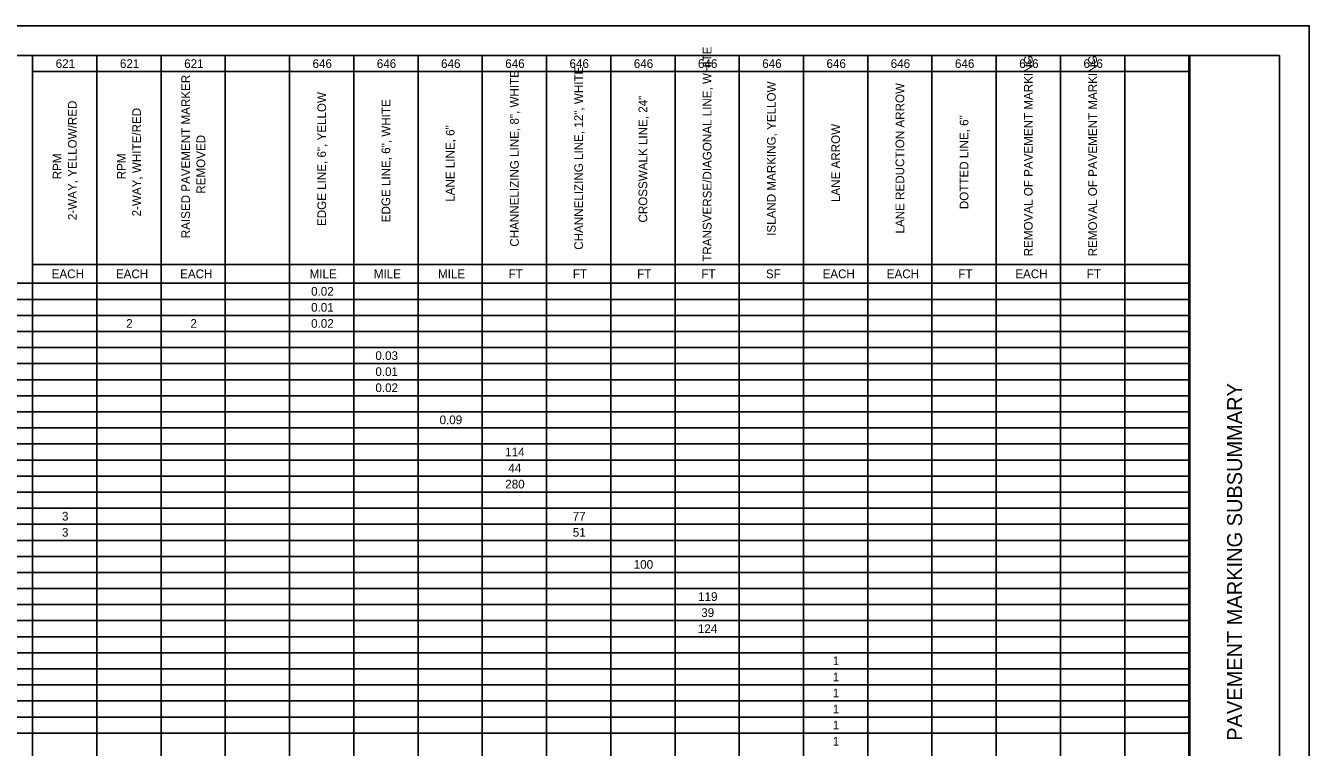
# Model space of a CAD drawing. Extents: x 0 to 34, y 0 to 22.
# Drawn here: x 12.53 to 34, y 9.93 to 22 of the extents above; entities that cross this region are included whole.
import ezdxf

# ---------------------------------------------------------------- set-up
doc = ezdxf.new("R2010")
doc.units = 0
for name, color, linetype in [('SH_Border', 7, 'Continuous'), ('SH_Cut_Line', 7, 'Continuous'), ('SH_Data', 7, 'Continuous'), ('SH_Text', 7, 'Continuous')]:
    doc.layers.add(name, color=color, linetype=linetype)

msp = doc.modelspace()

# ---------------------------------------------------------------- linework, layer by layer
at = {"layer": 'SH_Border'}
msp.add_line((32, 0.5), (32, 21.5), dxfattribs=at)
msp.add_lwpolyline([(1.5, 21.5), (33.5, 21.5), (33.5, 0.5), (1.5, 0.5)], close=True, dxfattribs=at)
at = {"layer": 'SH_Cut_Line'}
msp.add_lwpolyline([(0, 0), (34, 0), (34, 22), (0, 22)], close=True, dxfattribs=at)
at = {"layer": 'SH_Text'}
for p, q in [((1.5, 21.5), (31.986, 21.5)), ((12.642, 21.5), (12.642, 0.496)), ((13.717, 21.5), (13.717, 0.765)), ((14.791, 21.5), (14.791, 0.496)), ((15.866, 21.5), (15.866, 0.496)), ((16.941, 21.5), (16.941, 0.496)), ((18.015, 21.5), (18.015, 0.765)), ((19.09, 21.5), (19.09, 0.496)), ((20.165, 21.5), (20.165, 0.496)), ((21.239, 21.5), (21.239, 0.496)), ((22.314, 21.5), (22.314, 0.496)), ((23.389, 21.5), (23.389, 0.496)), ((24.463, 21.5), (24.463, 0.496)), ((25.538, 21.5), (25.538, 0.496)), ((26.613, 21.5), (26.613, 0.496)), ((27.687, 21.5), (27.687, 0.496)), ((28.762, 21.5), (28.762, 0.496)), ((29.837, 21.5), (29.837, 0.496)), ((30.911, 21.5), (30.911, 0.496)), ((31.986, 21.5), (31.986, 0.496)), ((12.642, 21.231), (31.986, 21.231)), ((12.642, 18.007), (31.986, 18.007)), ((1.5, 17.691), (31.986, 17.691)), ((1.5, 17.423), (31.986, 17.423)), ((1.5, 17.154), (31.986, 17.154)), ((1.5, 16.885), (31.986, 16.885)), ((1.5, 16.617), (31.986, 16.617)), ((1.5, 16.348), (31.986, 16.348)), ((1.5, 16.079), (31.986, 16.079)), ((1.5, 15.811), (31.986, 15.811)), ((1.5, 15.542), (31.986, 15.542)), ((1.5, 15.273), (31.986, 15.273)), ((1.5, 15.005), (31.986, 15.005)), ((1.5, 14.736), (31.986, 14.736)), ((1.5, 14.467), (31.986, 14.467)), ((1.5, 14.198), (31.986, 14.198)), ((1.5, 13.93), (31.986, 13.93)), ((1.5, 13.661), (31.986, 13.661)), ((1.5, 13.392), (31.986, 13.392)), ((1.5, 13.124), (31.986, 13.124)), ((1.5, 12.855), (31.986, 12.855)), ((1.5, 12.586), (31.986, 12.586)), ((1.5, 12.318), (31.986, 12.318)), ((1.5, 12.049), (31.986, 12.049)), ((1.5, 11.78), (31.986, 11.78)), ((1.5, 11.512), (31.986, 11.512)), ((1.5, 11.243), (31.986, 11.243)), ((1.5, 10.974), (31.986, 10.974)), ((1.5, 10.706), (31.986, 10.706)), ((1.5, 10.437), (31.986, 10.437)), ((1.5, 10.168), (31.986, 10.168))]:
    msp.add_line(p, q, dxfattribs=at)

# ---------------------------------------------------------------- texts
at = {"layer": 'SH_Data'}
msp.add_text('PAVEMENT MARKING SUBSUMMARY', height=0.25, rotation=90, dxfattribs=at).set_placement((32.875, 10.041))
at = {"layer": 'SH_Text'}
for s, p in [('TRANSVERSE/DIAGONAL LINE, WHITE', (23.999, 18.053)), ('REMOVAL OF PAVEMENT MARKING', (29.372, 18.143)), ('REMOVAL OF PAVEMENT MARKING', (30.447, 18.143)), ('CHANNELIZING LINE, 12", WHITE', (21.849, 18.252)), ('RAISED PAVEMENT MARKER ', (15.274, 18.445)), ('CHANNELIZING LINE, 8", WHITE', (20.775, 18.304)), ('ISLAND MARKING, YELLOW', (25.073, 18.485)), ('EDGE LINE, 6", YELLOW', (17.551, 18.649)), ('LANE REDUCTION ARROW', (27.223, 18.524)), ('2-WAY, YELLOW/RED', (13.379, 18.748)), ('2-WAY, WHITE/RED', (14.454, 18.81)), ('EDGE LINE, 6", WHITE', (18.625, 18.712)), ('CROSSWALK LINE, 24"', (22.924, 18.707)), ('DOTTED LINE, 6"', (28.297, 18.931)), ('LANE LINE, 6"', (19.7, 19.055)), ('LANE ARROW', (26.148, 19.05)), ('REMOVED', (15.529, 19.19)), ('RPM', (13.125, 19.431)), ('RPM', (14.199, 19.431))]:
    msp.add_text(s, height=0.1454, rotation=90, dxfattribs=at).set_placement(p)
for s, height, p in [('621', 0.1454, (13.028, 21.293)), ('621', 0.1454, (14.103, 21.293)), ('621', 0.1454, (15.178, 21.293)), ('646', 0.1454, (17.325, 21.293)), ('646', 0.1454, (18.4, 21.293)), ('646', 0.1454, (19.475, 21.293)), ('646', 0.1454, (20.549, 21.293)), ('646', 0.1454, (21.624, 21.293)), ('646', 0.1454, (22.699, 21.293)), ('646', 0.1454, (23.773, 21.293)), ('646', 0.1454, (24.848, 21.293)), ('646', 0.1454, (25.923, 21.293)), ('646', 0.1454, (26.997, 21.293)), ('646', 0.1454, (28.072, 21.293)), ('646', 0.1454, (29.147, 21.293)), ('646', 0.1454, (30.222, 21.293)), ('EACH', 0.1454, (12.961, 17.777)), ('EACH', 0.1454, (14.035, 17.777)), ('EACH', 0.1454, (15.11, 17.777)), ('MILE', 0.1454, (17.276, 17.777)), ('MILE', 0.1454, (18.35, 17.777)), ('MILE', 0.1454, (19.425, 17.777)), ('FT', 0.1454, (20.605, 17.777)), ('FT', 0.1454, (21.68, 17.777)), ('FT', 0.1454, (22.755, 17.777)), ('FT', 0.1454, (23.829, 17.777)), ('SF', 0.1454, (24.91, 17.777)), ('EACH', 0.1454, (25.857, 17.777)), ('EACH', 0.1454, (26.931, 17.777)), ('FT', 0.1454, (28.128, 17.777)), ('EACH', 0.1454, (29.081, 17.777)), ('FT', 0.1454, (30.277, 17.777)), ('0.02', 0.1454, (17.301, 17.484)), ('0.01', 0.1454, (17.301, 17.216)), ('2', 0.145, (14.207, 16.947)), ('2', 0.145, (15.282, 16.947)), ('0.02', 0.1454, (17.301, 16.947)), ('0.03', 0.1454, (18.376, 16.409)), ('0.01', 0.1454, (18.376, 16.141)), ('0.02', 0.1454, (18.376, 15.872)), ('0.09', 0.1454, (19.45, 15.335)), ('114', 0.1454, (20.548, 14.797)), ('44', 0.1454, (20.601, 14.529)), ('280', 0.1454, (20.549, 14.26)), ('3', 0.145, (13.133, 13.723)), ('77', 0.1454, (21.677, 13.723)), ('3', 0.145, (13.133, 13.454)), ('51', 0.1454, (21.678, 13.454)), ('100', 0.1454, (22.698, 12.917)), ('119', 0.1454, (23.775, 12.379)), ('39', 0.1454, (23.827, 12.111)), ('124', 0.1454, (23.772, 11.842)), ('1', 0.145, (26.029, 11.305)), ('1', 0.145, (26.029, 11.036)), ('1', 0.145, (26.029, 10.767)), ('1', 0.145, (26.029, 10.499)), ('1', 0.145, (26.029, 10.23)), ('1', 0.145, (26.029, 9.961))]:
    msp.add_text(s, height=height, dxfattribs=at).set_placement(p)

doc.saveas('drawing.dxf')
